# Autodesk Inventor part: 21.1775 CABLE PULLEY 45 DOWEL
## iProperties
Created: 2007-05
Part Number: 21.1775 CABLE PULLEY 45 DOWEL
Material: Steel
Document SubType Name: Modeling
Designer: Andy Moles
Density: 7.85 g/cm^3
Author: Andy Moles
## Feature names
1. Extrusion1
2. Fillet1
